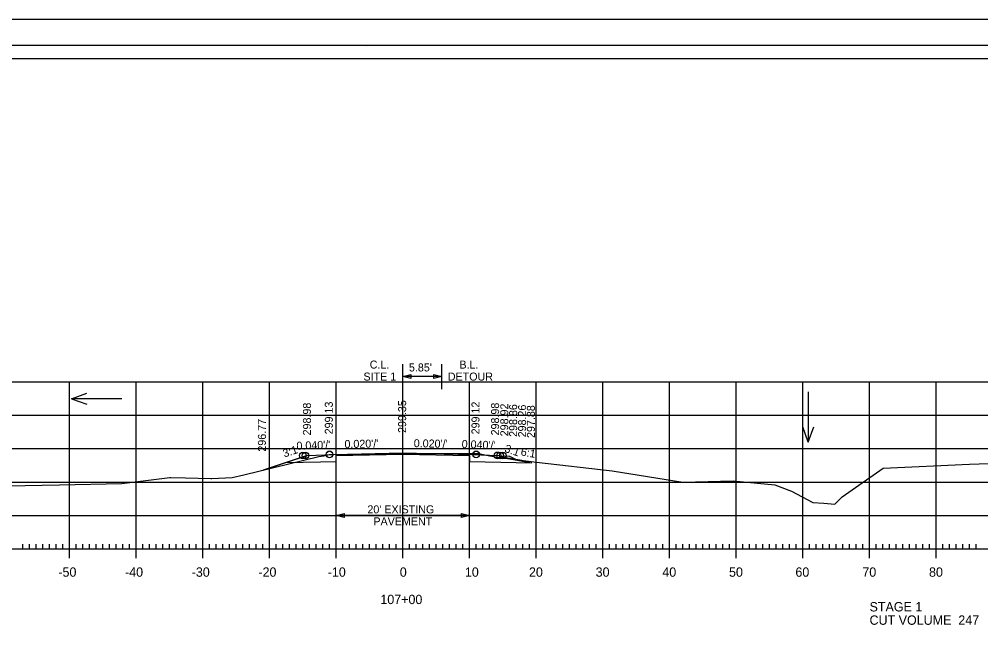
# Model space of a CAD drawing. Extents: x 1368713 to 1370673, y 380279 to 380950.
# Drawn here: x 1370094.8 to 1370239, y 380646.1 to 380737.1 of the extents above; entities that cross this region are included whole.
import ezdxf

# ---------------------------------------------------------------- set-up
doc = ezdxf.new("R2010")
doc.units = 0
for name, color, linetype in [('R_Alt Surface', 7, 'Continuous'), ('R_Axis', 7, 'Continuous'), ('R_Axis Annot', 7, 'Continuous'), ('R_Border', 7, 'Continuous'), ('R_Exist Surface', 7, 'Continuous'), ('R_Fin Surface', 7, 'Continuous'), ('R_Grid', 7, 'Continuous'), ('R_No Plot', 7, 'Continuous'), ('R_ROW Annot', 7, 'Continuous'), ('R_Water Annot', 7, 'Continuous'), ('R_Xsect Elev', 7, 'Continuous'), ('R_Xsect Slope', 7, 'Continuous')]:
    doc.layers.add(name, color=color, linetype=linetype)

msp = doc.modelspace()

# ---------------------------------------------------------------- linework, layer by layer
for points in [[(1370141.28, 380671.89), (1370141.28, 380671.89), (1370141.28, 380671.88), (1370141.28, 380671.88), (1370141.28, 380671.87)], [(1370163.28, 380671.89), (1370163.28, 380671.88), (1370163.28, 380671.88), (1370163.28, 380671.87)]]:
    msp.add_lwpolyline(points)
at = {"layer": 'R_Alt Surface'}
for points in [[(1370137.95, 380671.73), (1370137.95, 380671.73), (1370131.33, 380669.53)], [(1370134.75, 380670.67), (1370139.95, 380670.77), (1370142.27, 380670.82), (1370142.28, 380671.73), (1370152.28, 380671.93), (1370162.28, 380671.73), (1370162.29, 380670.82), (1370164.62, 380670.77), (1370171.64, 380670.63)], [(1370166.62, 380671.73), (1370166.62, 380671.73), (1370168.01, 380671.27)], [(1370170.12, 380670.95), (1370169.54, 380671.06), (1370169.02, 380671.14), (1370168.34, 380671.25), (1370167.64, 380671.36)], [(1370168.28, 380671.61), (1370168.28, 380671.61), (1370169.49, 380671.01)], [(1370126.81, 380668.41), (1370126.81, 380668.41)], [(1370127.93, 380668.69), (1370127.93, 380668.69)], [(1370129.04, 380668.97), (1370129.04, 380668.97)], [(1370130.38, 380669.3), (1370130.38, 380669.3)]]:
    msp.add_lwpolyline(points, dxfattribs=at)
at = {"layer": 'R_Axis'}
for p, q in [((1370095.28, 380657.75), (1370095.28, 380658.45)), ((1370096.28, 380657.75), (1370096.28, 380658.45)), ((1370097.28, 380657.75), (1370097.28, 380658.45)), ((1370098.28, 380657.75), (1370098.28, 380658.45)), ((1370099.28, 380657.75), (1370099.28, 380658.45)), ((1370100.28, 380657.75), (1370100.28, 380658.45)), ((1370101.28, 380657.75), (1370101.28, 380658.45)), ((1370102.28, 380656.35), (1370102.28, 380659.15)), ((1370103.28, 380657.75), (1370103.28, 380658.45)), ((1370104.28, 380657.75), (1370104.28, 380658.45)), ((1370105.28, 380657.75), (1370105.28, 380658.45)), ((1370106.28, 380657.75), (1370106.28, 380658.45)), ((1370107.28, 380657.75), (1370107.28, 380658.45)), ((1370108.28, 380657.75), (1370108.28, 380658.45)), ((1370109.28, 380657.75), (1370109.28, 380658.45)), ((1370110.28, 380657.75), (1370110.28, 380658.45)), ((1370111.28, 380657.75), (1370111.28, 380658.45)), ((1370112.28, 380656.35), (1370112.28, 380659.15)), ((1370113.28, 380657.75), (1370113.28, 380658.45)), ((1370114.28, 380657.75), (1370114.28, 380658.45)), ((1370115.28, 380657.75), (1370115.28, 380658.45)), ((1370116.28, 380657.75), (1370116.28, 380658.45)), ((1370117.28, 380657.75), (1370117.28, 380658.45)), ((1370118.28, 380657.75), (1370118.28, 380658.45)), ((1370119.28, 380657.75), (1370119.28, 380658.45)), ((1370120.28, 380657.75), (1370120.28, 380658.45)), ((1370121.28, 380657.75), (1370121.28, 380658.45)), ((1370122.28, 380656.35), (1370122.28, 380659.15)), ((1370123.28, 380657.75), (1370123.28, 380658.45)), ((1370124.28, 380657.75), (1370124.28, 380658.45)), ((1370125.28, 380657.75), (1370125.28, 380658.45)), ((1370126.28, 380657.75), (1370126.28, 380658.45)), ((1370127.28, 380657.75), (1370127.28, 380658.45)), ((1370128.28, 380657.75), (1370128.28, 380658.45)), ((1370129.28, 380657.75), (1370129.28, 380658.45)), ((1370130.28, 380657.75), (1370130.28, 380658.45)), ((1370131.28, 380657.75), (1370131.28, 380658.45)), ((1370132.28, 380656.35), (1370132.28, 380659.15)), ((1370133.28, 380657.75), (1370133.28, 380658.45)), ((1370134.28, 380657.75), (1370134.28, 380658.45)), ((1370135.28, 380657.75), (1370135.28, 380658.45)), ((1370136.28, 380657.75), (1370136.28, 380658.45)), ((1370137.28, 380657.75), (1370137.28, 380658.45)), ((1370138.28, 380657.75), (1370138.28, 380658.45)), ((1370139.28, 380657.75), (1370139.28, 380658.45)), ((1370140.28, 380657.75), (1370140.28, 380658.45)), ((1370141.28, 380657.75), (1370141.28, 380658.45)), ((1370142.28, 380656.35), (1370142.28, 380659.15)), ((1370143.28, 380657.75), (1370143.28, 380658.45)), ((1370144.28, 380657.75), (1370144.28, 380658.45)), ((1370145.28, 380657.75), (1370145.28, 380658.45)), ((1370146.28, 380657.75), (1370146.28, 380658.45)), ((1370147.28, 380657.75), (1370147.28, 380658.45)), ((1370148.28, 380657.75), (1370148.28, 380658.45)), ((1370149.28, 380657.75), (1370149.28, 380658.45)), ((1370150.28, 380657.75), (1370150.28, 380658.45)), ((1370151.28, 380657.75), (1370151.28, 380658.45)), ((1370152.28, 380656.35), (1370152.28, 380659.15)), ((1370153.28, 380657.75), (1370153.28, 380658.45)), ((1370154.28, 380657.75), (1370154.28, 380658.45)), ((1370155.28, 380657.75), (1370155.28, 380658.45)), ((1370156.28, 380657.75), (1370156.28, 380658.45)), ((1370157.28, 380657.75), (1370157.28, 380658.45)), ((1370158.28, 380657.75), (1370158.28, 380658.45)), ((1370159.28, 380657.75), (1370159.28, 380658.45)), ((1370160.28, 380657.75), (1370160.28, 380658.45)), ((1370161.28, 380657.75), (1370161.28, 380658.45)), ((1370162.28, 380656.35), (1370162.28, 380659.15)), ((1370163.28, 380657.75), (1370163.28, 380658.45)), ((1370164.28, 380657.75), (1370164.28, 380658.45)), ((1370165.28, 380657.75), (1370165.28, 380658.45)), ((1370166.28, 380657.75), (1370166.28, 380658.45)), ((1370167.28, 380657.75), (1370167.28, 380658.45)), ((1370168.28, 380657.75), (1370168.28, 380658.45)), ((1370169.28, 380657.75), (1370169.28, 380658.45)), ((1370170.28, 380657.75), (1370170.28, 380658.45)), ((1370171.28, 380657.75), (1370171.28, 380658.45)), ((1370172.28, 380656.35), (1370172.28, 380659.15)), ((1370173.28, 380657.75), (1370173.28, 380658.45)), ((1370174.28, 380657.75), (1370174.28, 380658.45)), ((1370175.28, 380657.75), (1370175.28, 380658.45)), ((1370176.28, 380657.75), (1370176.28, 380658.45)), ((1370177.28, 380657.75), (1370177.28, 380658.45)), ((1370178.28, 380657.75), (1370178.28, 380658.45)), ((1370179.28, 380657.75), (1370179.28, 380658.45)), ((1370180.28, 380657.75), (1370180.28, 380658.45)), ((1370181.28, 380657.75), (1370181.28, 380658.45)), ((1370182.28, 380656.35), (1370182.28, 380659.15)), ((1370183.28, 380657.75), (1370183.28, 380658.45)), ((1370184.28, 380657.75), (1370184.28, 380658.45)), ((1370185.28, 380657.75), (1370185.28, 380658.45)), ((1370186.28, 380657.75), (1370186.28, 380658.45)), ((1370187.28, 380657.75), (1370187.28, 380658.45)), ((1370188.28, 380657.75), (1370188.28, 380658.45)), ((1370189.28, 380657.75), (1370189.28, 380658.45)), ((1370190.28, 380657.75), (1370190.28, 380658.45)), ((1370191.28, 380657.75), (1370191.28, 380658.45)), ((1370192.28, 380656.35), (1370192.28, 380659.15)), ((1370193.28, 380657.75), (1370193.28, 380658.45)), ((1370194.28, 380657.75), (1370194.28, 380658.45)), ((1370195.28, 380657.75), (1370195.28, 380658.45)), ((1370196.28, 380657.75), (1370196.28, 380658.45)), ((1370197.28, 380657.75), (1370197.28, 380658.45)), ((1370198.28, 380657.75), (1370198.28, 380658.45)), ((1370199.28, 380657.75), (1370199.28, 380658.45)), ((1370200.28, 380657.75), (1370200.28, 380658.45)), ((1370201.28, 380657.75), (1370201.28, 380658.45)), ((1370202.28, 380656.35), (1370202.28, 380659.15)), ((1370203.28, 380657.75), (1370203.28, 380658.45)), ((1370204.28, 380657.75), (1370204.28, 380658.45)), ((1370205.28, 380657.75), (1370205.28, 380658.45)), ((1370206.28, 380657.75), (1370206.28, 380658.45)), ((1370207.28, 380657.75), (1370207.28, 380658.45)), ((1370208.28, 380657.75), (1370208.28, 380658.45)), ((1370209.28, 380657.75), (1370209.28, 380658.45)), ((1370210.28, 380657.75), (1370210.28, 380658.45)), ((1370211.28, 380657.75), (1370211.28, 380658.45)), ((1370212.28, 380656.35), (1370212.28, 380659.15)), ((1370213.28, 380657.75), (1370213.28, 380658.45)), ((1370214.28, 380657.75), (1370214.28, 380658.45)), ((1370215.28, 380657.75), (1370215.28, 380658.45)), ((1370216.28, 380657.75), (1370216.28, 380658.45)), ((1370217.28, 380657.75), (1370217.28, 380658.45)), ((1370218.28, 380657.75), (1370218.28, 380658.45)), ((1370219.28, 380657.75), (1370219.28, 380658.45)), ((1370220.28, 380657.75), (1370220.28, 380658.45)), ((1370221.28, 380657.75), (1370221.28, 380658.45)), ((1370222.28, 380656.35), (1370222.28, 380659.15)), ((1370223.28, 380657.75), (1370223.28, 380658.45)), ((1370224.28, 380657.75), (1370224.28, 380658.45)), ((1370225.28, 380657.75), (1370225.28, 380658.45)), ((1370226.28, 380657.75), (1370226.28, 380658.45)), ((1370227.28, 380657.75), (1370227.28, 380658.45)), ((1370228.28, 380657.75), (1370228.28, 380658.45)), ((1370229.28, 380657.75), (1370229.28, 380658.45)), ((1370230.28, 380657.75), (1370230.28, 380658.45)), ((1370231.28, 380657.75), (1370231.28, 380658.45)), ((1370232.28, 380656.35), (1370232.28, 380659.15)), ((1370233.28, 380657.75), (1370233.28, 380658.45)), ((1370234.28, 380657.75), (1370234.28, 380658.45)), ((1370235.28, 380657.75), (1370235.28, 380658.45)), ((1370236.28, 380657.75), (1370236.28, 380658.45)), ((1370237.28, 380657.75), (1370237.28, 380658.45)), ((1370238.28, 380657.75), (1370238.28, 380658.45)), ((1370012.28, 380657.75), (1370292.28, 380657.75))]:
    msp.add_line(p, q, dxfattribs=at)
at = {"layer": 'R_Border'}
for p, q in [((1369994.28, 380733.21), (1370310.46, 380733.21)), ((1370146.8, 380732.95), (1370146.8, 380732.95)), ((1370146.8, 380732.95), (1370146.8, 380732.95))]:
    msp.add_line(p, q, dxfattribs=at)
at = {"layer": 'R_Exist Surface'}
msp.add_lwpolyline([(1370069.74, 380666.74), (1370100.77, 380667.35), (1370110.16, 380667.53), (1370117.32, 380668.41), (1370117.49, 380668.43), (1370119.69, 380668.36), (1370123.5, 380668.25), (1370123.62, 380668.26), (1370126.68, 380668.4), (1370128.42, 380668.82), (1370139.67, 380671.55), (1370140.42, 380671.68), (1370141.25, 380671.87), (1370147.78, 380671.94), (1370152.18, 380672.02), (1370156.87, 380672), (1370163.69, 380672), (1370164.85, 380671.79), (1370166.39, 380671.47), (1370172.33, 380670.72), (1370183.68, 380669.43), (1370194.3, 380667.73), (1370201.83, 380667.93), (1370208.06, 380667.32), (1370210.56, 380666.38), (1370213.75, 380664.7), (1370215.41, 380664.59), (1370217.09, 380664.41), (1370218.15, 380665.51), (1370224.31, 380669.8), (1370237.27, 380670.42), (1370244.58, 380670.65)], dxfattribs=at)
at = {"layer": 'R_Fin Surface'}
for points in [[(1370131.33, 380669.53), (1370134.75, 380670.67), (1370137.95, 380671.73), (1370141.95, 380671.89), (1370152.28, 380672.1), (1370162.62, 380671.89), (1370166.62, 380671.73), (1370168.01, 380671.27), (1370171.64, 380670.63)], [(1370137.95, 380671.73), (1370141.95, 380671.89), (1370152.28, 380672.1), (1370162.62, 380671.89), (1370166.62, 380671.73)], [(1370166.81, 380671.67), (1370168.28, 380671.61)]]:
    msp.add_lwpolyline(points, dxfattribs=at)
at = {"layer": 'R_Grid'}
for p, q in [((1370012.28, 380682.75), (1370292.28, 380682.75)), ((1370102.28, 380657.75), (1370102.28, 380682.75)), ((1370112.28, 380657.75), (1370112.28, 380682.75)), ((1370122.28, 380657.75), (1370122.28, 380682.75)), ((1370132.28, 380657.75), (1370132.28, 380682.75)), ((1370142.28, 380657.75), (1370142.28, 380682.75)), ((1370152.28, 380657.75), (1370152.28, 380682.75)), ((1370162.28, 380657.75), (1370162.28, 380682.75)), ((1370172.28, 380657.75), (1370172.28, 380682.75)), ((1370182.28, 380657.75), (1370182.28, 380682.75)), ((1370192.28, 380657.75), (1370192.28, 380682.75)), ((1370202.28, 380657.75), (1370202.28, 380682.75)), ((1370212.28, 380657.75), (1370212.28, 380682.75)), ((1370222.28, 380657.75), (1370222.28, 380682.75)), ((1370232.28, 380657.75), (1370232.28, 380682.75)), ((1370012.28, 380677.75), (1370292.28, 380677.75)), ((1370012.28, 380672.75), (1370292.28, 380672.75)), ((1370012.28, 380667.75), (1370292.28, 380667.75)), ((1370012.28, 380662.75), (1370292.28, 380662.75)), ((1370012.28, 380657.75), (1370292.28, 380657.75))]:
    msp.add_line(p, q, dxfattribs=at)
at = {"layer": 'R_No Plot'}
for points in [[(1369981.88, 380737.11), (1370315.22, 380737.11), (1370315.22, 380523.77), (1369981.88, 380523.77)], [(1370308.46, 380632.48), (1369996.28, 380632.48), (1369996.28, 380731.21), (1370245.82, 380731.21), (1370245.82, 380721.33), (1370263.36, 380721.33), (1370287.46, 380721.33), (1370287.46, 380699), (1370308.46, 380699)], [(1369996.28, 380731.21), (1370245.82, 380731.21), (1370245.82, 380721.33), (1370263.36, 380721.33), (1370287.46, 380721.33), (1370287.46, 380699), (1370308.46, 380699), (1370308.46, 380529.75), (1369996.28, 380529.75)]]:
    msp.add_lwpolyline(points, close=True, dxfattribs=at)
for centre in [(1370137.28, 380671.73), (1370137.28, 380671.72), (1370137.28, 380671.72), (1370137.68, 380671.73), (1370141.28, 380671.89), (1370141.28, 380671.88), (1370141.28, 380671.88), (1370141.28, 380671.88), (1370141.28, 380671.87), (1370163.28, 380671.89), (1370163.28, 380671.88), (1370163.28, 380671.88), (1370163.28, 380671.88), (1370163.28, 380671.87), (1370166.48, 380671.74), (1370166.88, 380671.73), (1370167.28, 380671.73), (1370167.28, 380671.72), (1370167.28, 380671.72)]:
    msp.add_circle(centre, 0.5, dxfattribs=at)
at = {"layer": 'R_ROW Annot'}
for p, q in [((1370152.28, 380681.67), (1370152.28, 380685.43)), ((1370158.13, 380681.67), (1370158.13, 380685.43)), ((1370158.13, 380683.55), (1370152.28, 380683.55)), ((1370142.28, 380660.87), (1370142.28, 380664.64)), ((1370162.28, 380660.87), (1370162.28, 380664.64)), ((1370162.28, 380662.75), (1370142.28, 380662.75))]:
    msp.add_line(p, q, dxfattribs=at)
for points in [[(1370153.48, 380683.25), (1370152.28, 380683.55), (1370153.48, 380683.85)], [(1370156.93, 380683.85), (1370158.13, 380683.55), (1370156.93, 380683.25)], [(1370143.48, 380662.45), (1370142.28, 380662.75), (1370143.48, 380663.05)], [(1370161.08, 380663.05), (1370162.28, 380662.75), (1370161.08, 380662.45)]]:
    msp.add_lwpolyline(points, close=True, dxfattribs=at)
at = {"layer": 'R_Water Annot'}
for p, q in [((1370102.59, 380680.24), (1370104.9, 380681.08)), ((1370110.13, 380680.24), (1370102.59, 380680.24)), ((1370102.59, 380680.24), (1370104.9, 380679.4)), ((1370213.09, 380681.25), (1370213.09, 380673.71)), ((1370213.09, 380673.71), (1370212.25, 380676.01)), ((1370213.09, 380673.71), (1370213.93, 380676.01))]:
    msp.add_line(p, q, dxfattribs=at)

# ---------------------------------------------------------------- texts
at = {"layer": 'R_Axis Annot'}
for s, p in [('-50', (1370100.62, 380653.55)), ('-40', (1370110.62, 380653.55)), ('-30', (1370120.62, 380653.55)), ('-20', (1370130.62, 380653.55)), ('-10', (1370141.02, 380653.55)), ('0', (1370151.83, 380653.55)), ('10', (1370161.59, 380653.55)), ('20', (1370171.2, 380653.55)), ('30', (1370181.2, 380653.55)), ('40', (1370191.2, 380653.55)), ('50', (1370201.2, 380653.55)), ('60', (1370211.16, 380653.55)), ('70', (1370221.2, 380653.55)), ('80', (1370231.2, 380653.55)), ('107+00', (1370148.91, 380649.45)), ('STAGE 1', (1370222.28, 380648.35)), ('CUT VOLUME  247', (1370222.28, 380646.35))]:
    msp.add_text(s, height=1.4, dxfattribs=at).set_placement(p)
at = {"layer": 'R_ROW Annot'}
for s, p in [('C.L.', (1370147.32, 380684.75)), ('B.L.', (1370160.77, 380684.75)), ('SITE 1', (1370146.38, 380682.95)), ("5.85'", (1370153.2, 380684.32)), ('DETOUR', (1370159.03, 380682.95)), ("20' EXISTING", (1370146.97, 380663.05)), ('PAVEMENT', (1370147.87, 380661.25))]:
    msp.add_text(s, height=1.2, dxfattribs=at).set_placement(p)
at = {"layer": 'R_Xsect Elev'}
for s, p in [('299.35', (1370152.78, 380675.1)), ('298.98', (1370138.5, 380674.73)), ('299.13', (1370141.78, 380674.89)), ('299.12', (1370163.78, 380674.89)), ('298.98', (1370166.72, 380674.73)), ('298.92', (1370168.1, 380674.6)), ('298.86', (1370169.43, 380674.51)), ('298.26', (1370170.77, 380674.44)), ('297.88', (1370172.09, 380674.35)), ('296.77', (1370131.75, 380672.3))]:
    msp.add_text(s, height=1.2, rotation=90, dxfattribs=at).set_placement(p)
at = {"layer": 'R_Xsect Slope'}
for s, rotation, p in [("0.020'/'", 1.1458, (1370143.54, 380672.83)), ("0.020'/'", 358.8542, (1370153.91, 380672.97)), ('3:1', 18.4349, (1370134.51, 380671.41)), ("0.040'/'", 2.2906, (1370136.35, 380672.57)), ("0.040'/'", 357.7094, (1370161.09, 380672.86)), ('3:1', 341.5651, (1370167.44, 380672.28)), ('6:1', 350.0356, (1370169.9, 380671.74))]:
    msp.add_text(s, height=1.2, rotation=rotation, dxfattribs=at).set_placement(p)

doc.saveas('drawing.dxf')
